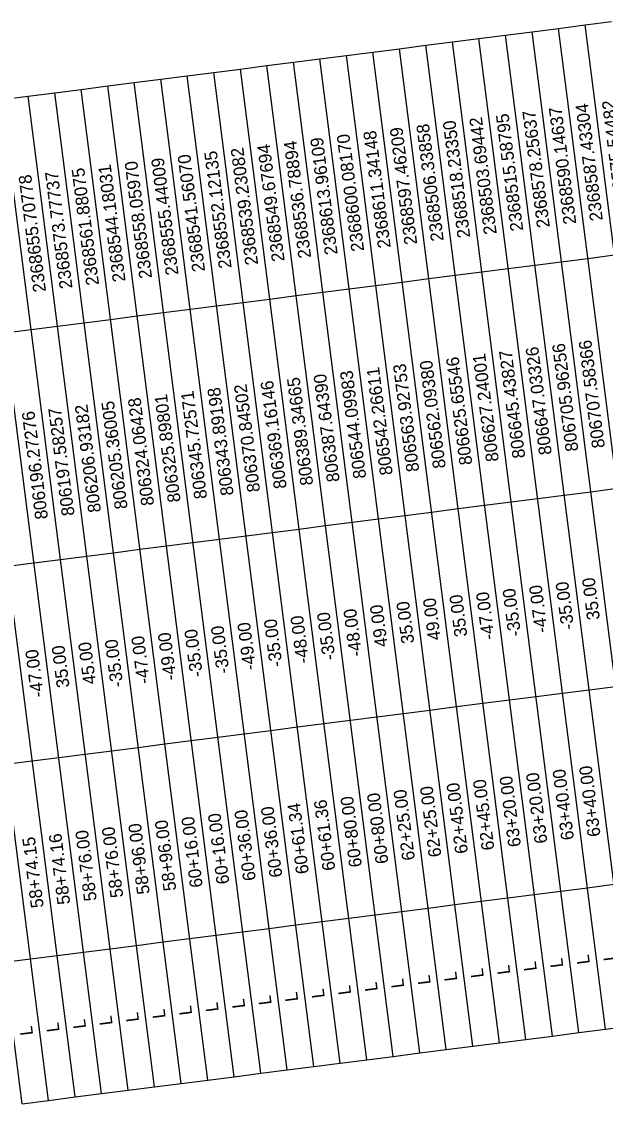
# Model space of a CAD drawing. Extents: x 2364621 to 2374814, y 792603 to 806745.
# Drawn here: x 2368118 to 2369200, y 803235 to 805232 of the extents above; entities that cross this region are included whole.
import ezdxf

# ---------------------------------------------------------------- set-up
doc = ezdxf.new("R2010")
doc.units = 0
doc.layers.add('CTL Sheet Table Cell', color=7, linetype='Continuous')
doc.layers.add('CTL Sheet Text', color=7, linetype='Continuous')

msp = doc.modelspace()

# ---------------------------------------------------------------- linework, layer by layer
at = {"layer": 'CTL Sheet Table Cell'}
for p, q in [((2369063.9, 805212.7), (2369113, 805219)), ((2369113, 805219), (2369162.1, 805225.3)), ((2369347.2, 803385.2), (2369113, 805219)), ((2369162.1, 805225.3), (2369211.2, 805231.5)), ((2369396.3, 803391.5), (2369162.1, 805225.3)), ((2368916.5, 805193.9), (2368965.6, 805200.2)), ((2368965.6, 805200.2), (2369014.8, 805206.4)), ((2369199.8, 803366.4), (2368965.6, 805200.2)), ((2369014.8, 805206.4), (2369063.9, 805212.7)), ((2369249, 803372.7), (2369014.8, 805206.4)), ((2369298.1, 803379), (2369063.9, 805212.7)), ((2368769.2, 805175.1), (2368818.3, 805181.3)), ((2368818.3, 805181.3), (2368867.4, 805187.6)), ((2369052.5, 803347.6), (2368818.3, 805181.3)), ((2368867.4, 805187.6), (2368916.5, 805193.9)), ((2369101.6, 803353.9), (2368867.4, 805187.6)), ((2369150.7, 803360.2), (2368916.5, 805193.9)), ((2368621.8, 805156.2), (2368670.9, 805162.5)), ((2368670.9, 805162.5), (2368720.1, 805168.8)), ((2368905.1, 803328.8), (2368670.9, 805162.5)), ((2368720.1, 805168.8), (2368769.2, 805175.1)), ((2368954.3, 803335.1), (2368720.1, 805168.8)), ((2369003.4, 803341.3), (2368769.2, 805175.1)), ((2368425.3, 805131.2), (2368474.5, 805137.4)), ((2368474.5, 805137.4), (2368523.6, 805143.7)), ((2368708.7, 803303.7), (2368474.5, 805137.4)), ((2368523.6, 805143.7), (2368572.7, 805150)), ((2368757.8, 803310), (2368523.6, 805143.7)), ((2368572.7, 805150), (2368621.8, 805156.2)), ((2368806.9, 803316.2), (2368572.7, 805150)), ((2368856, 803322.5), (2368621.8, 805156.2)), ((2368278, 805112.3), (2368327.1, 805118.6)), ((2368327.1, 805118.6), (2368376.2, 805124.9)), ((2368561.3, 803284.9), (2368327.1, 805118.6)), ((2368376.2, 805124.9), (2368425.3, 805131.2)), ((2368610.4, 803291.1), (2368376.2, 805124.9)), ((2368659.6, 803297.4), (2368425.3, 805131.2)), ((2368130.6, 805093.5), (2368179.8, 805099.8)), ((2368179.8, 805099.8), (2368228.9, 805106.1)), ((2368414, 803266.1), (2368179.8, 805099.8)), ((2368228.9, 805106.1), (2368278, 805112.3)), ((2368463.1, 803272.3), (2368228.9, 805106.1)), ((2368512.2, 803278.6), (2368278, 805112.3)), ((2368266.6, 803247.2), (2368032.4, 805081)), ((2368081.5, 805087.2), (2368130.6, 805093.5)), ((2368315.7, 803253.5), (2368081.5, 805087.2)), ((2368364.8, 803259.8), (2368130.6, 805093.5)), ((2368119.3, 803228.4), (2367885.1, 805062.2)), ((2368168.4, 803234.7), (2367934.2, 805068.4)), ((2368217.5, 803241), (2367983.3, 805074.7)), ((2369167.4, 804793.3), (2369216.5, 804799.6)), ((2369020, 804774.5), (2369069.1, 804780.7)), ((2369069.1, 804780.7), (2369118.2, 804787)), ((2369118.2, 804787), (2369167.4, 804793.3)), ((2368872.7, 804755.7), (2368921.8, 804761.9)), ((2368921.8, 804761.9), (2368970.9, 804768.2)), ((2368970.9, 804768.2), (2369020, 804774.5)), ((2368725.3, 804736.8), (2368774.4, 804743.1)), ((2368774.4, 804743.1), (2368823.5, 804749.4)), ((2368823.5, 804749.4), (2368872.7, 804755.7)), ((2368528.8, 804711.7), (2368578, 804718)), ((2368578, 804718), (2368627.1, 804724.3)), ((2368627.1, 804724.3), (2368676.2, 804730.6)), ((2368676.2, 804730.6), (2368725.3, 804736.8)), ((2368381.5, 804692.9), (2368430.6, 804699.2)), ((2368430.6, 804699.2), (2368479.7, 804705.5)), ((2368479.7, 804705.5), (2368528.8, 804711.7)), ((2368234.1, 804674.1), (2368283.2, 804680.4)), ((2368283.2, 804680.4), (2368332.4, 804686.6)), ((2368332.4, 804686.6), (2368381.5, 804692.9)), ((2368086.8, 804655.3), (2368135.9, 804661.6)), ((2368135.9, 804661.6), (2368185, 804667.8)), ((2368185, 804667.8), (2368234.1, 804674.1)), ((2369123.5, 804355.1), (2369172.6, 804361.3)), ((2369172.6, 804361.3), (2369221.7, 804367.6)), ((2368976.1, 804336.2), (2369025.3, 804342.5)), ((2369025.3, 804342.5), (2369074.4, 804348.8)), ((2369074.4, 804348.8), (2369123.5, 804355.1)), ((2368828.8, 804317.4), (2368877.9, 804323.7)), ((2368877.9, 804323.7), (2368927, 804330)), ((2368927, 804330), (2368976.1, 804336.2)), ((2368632.3, 804292.3), (2368681.4, 804298.6)), ((2368681.4, 804298.6), (2368730.6, 804304.9)), ((2368730.6, 804304.9), (2368779.7, 804311.1)), ((2368779.7, 804311.1), (2368828.8, 804317.4)), ((2368485, 804273.5), (2368534.1, 804279.8)), ((2368534.1, 804279.8), (2368583.2, 804286.1)), ((2368583.2, 804286.1), (2368632.3, 804292.3)), ((2368337.6, 804254.7), (2368386.7, 804261)), ((2368386.7, 804261), (2368435.8, 804267.2)), ((2368435.8, 804267.2), (2368485, 804273.5)), ((2368190.3, 804235.9), (2368239.4, 804242.1)), ((2368239.4, 804242.1), (2368288.5, 804248.4)), ((2368288.5, 804248.4), (2368337.6, 804254.7)), ((2368092, 804223.3), (2368141.1, 804229.6)), ((2368141.1, 804229.6), (2368190.3, 804235.9)), ((2369169.5, 803994.9), (2369218.6, 804001.1)), ((2369022.1, 803976), (2369071.3, 803982.3)), ((2369071.3, 803982.3), (2369120.4, 803988.6)), ((2369120.4, 803988.6), (2369169.5, 803994.9)), ((2368874.8, 803957.2), (2368923.9, 803963.5)), ((2368923.9, 803963.5), (2368973, 803969.8)), ((2368973, 803969.8), (2369022.1, 803976)), ((2368727.4, 803938.4), (2368776.6, 803944.7)), ((2368776.6, 803944.7), (2368825.7, 803950.9)), ((2368825.7, 803950.9), (2368874.8, 803957.2)), ((2368531, 803913.3), (2368580.1, 803919.6)), ((2368580.1, 803919.6), (2368629.2, 803925.9)), ((2368629.2, 803925.9), (2368678.3, 803932.1)), ((2368678.3, 803932.1), (2368727.4, 803938.4)), ((2368383.6, 803894.5), (2368432.7, 803900.8)), ((2368432.7, 803900.8), (2368481.9, 803907)), ((2368481.9, 803907), (2368531, 803913.3)), ((2368236.3, 803875.7), (2368285.4, 803881.9)), ((2368285.4, 803881.9), (2368334.5, 803888.2)), ((2368334.5, 803888.2), (2368383.6, 803894.5)), ((2368088.9, 803856.8), (2368138, 803863.1)), ((2368138, 803863.1), (2368187.1, 803869.4)), ((2368187.1, 803869.4), (2368236.3, 803875.7)), ((2369068.2, 803615.8), (2369117.3, 803622.1)), ((2369117.3, 803622.1), (2369166.4, 803628.4)), ((2369166.4, 803628.4), (2369215.5, 803634.7)), ((2368920.8, 803597), (2368969.9, 803603.3)), ((2368969.9, 803603.3), (2369019, 803609.6)), ((2369019, 803609.6), (2369068.2, 803615.8)), ((2368773.4, 803578.2), (2368822.6, 803584.5)), ((2368822.6, 803584.5), (2368871.7, 803590.7)), ((2368871.7, 803590.7), (2368920.8, 803597)), ((2368626.1, 803559.4), (2368675.2, 803565.7)), ((2368675.2, 803565.7), (2368724.3, 803571.9)), ((2368724.3, 803571.9), (2368773.4, 803578.2)), ((2368429.6, 803534.3), (2368478.7, 803540.6)), ((2368478.7, 803540.6), (2368527.9, 803546.8)), ((2368527.9, 803546.8), (2368577, 803553.1)), ((2368577, 803553.1), (2368626.1, 803559.4)), ((2368282.3, 803515.5), (2368331.4, 803521.7)), ((2368331.4, 803521.7), (2368380.5, 803528)), ((2368380.5, 803528), (2368429.6, 803534.3)), ((2368134.9, 803496.7), (2368184, 803502.9)), ((2368184, 803502.9), (2368233.1, 803509.2)), ((2368233.1, 803509.2), (2368282.3, 803515.5)), ((2368085.8, 803490.4), (2368134.9, 803496.7)), ((2369101.6, 803353.9), (2369150.7, 803360.2)), ((2369150.7, 803360.2), (2369199.8, 803366.4)), ((2369199.8, 803366.4), (2369249, 803372.7)), ((2368954.3, 803335.1), (2369003.4, 803341.3)), ((2369003.4, 803341.3), (2369052.5, 803347.6)), ((2369052.5, 803347.6), (2369101.6, 803353.9)), ((2368806.9, 803316.2), (2368856, 803322.5)), ((2368856, 803322.5), (2368905.1, 803328.8)), ((2368905.1, 803328.8), (2368954.3, 803335.1)), ((2368659.6, 803297.4), (2368708.7, 803303.7)), ((2368708.7, 803303.7), (2368757.8, 803310)), ((2368757.8, 803310), (2368806.9, 803316.2)), ((2368512.2, 803278.6), (2368561.3, 803284.9)), ((2368561.3, 803284.9), (2368610.4, 803291.1)), ((2368610.4, 803291.1), (2368659.6, 803297.4)), ((2368364.8, 803259.8), (2368414, 803266.1)), ((2368414, 803266.1), (2368463.1, 803272.3)), ((2368463.1, 803272.3), (2368512.2, 803278.6)), ((2368168.4, 803234.7), (2368217.5, 803241)), ((2368217.5, 803241), (2368266.6, 803247.2)), ((2368266.6, 803247.2), (2368315.7, 803253.5)), ((2368315.7, 803253.5), (2368364.8, 803259.8)), ((2368119.3, 803228.4), (2368168.4, 803234.7))]:
    msp.add_line(p, q, dxfattribs=at)

# ---------------------------------------------------------------- texts
at = {"layer": 'CTL Sheet Text'}
for s, height, p in [('2368587.43304', 23.579, (2369195.2, 804863.8)), ('2368575.54482', 23.579, (2369244.3, 804870.1)), ('2368515.58795', 23.579, (2369047.9, 804845)), ('2368578.25637', 23.579, (2369097, 804851.3)), ('2368590.14637', 23.579, (2369146.1, 804857.5)), ('2368506.33858', 23.579, (2368900.5, 804826.2)), ('2368518.23350', 23.579, (2368949.6, 804832.4)), ('2368503.69442', 23.579, (2368998.7, 804838.7)), ('2368600.08170', 23.579, (2368753.1, 804807.3)), ('2368611.34148', 23.579, (2368802.3, 804813.6)), ('2368597.46209', 23.579, (2368851.4, 804819.9)), ('2368539.23082', 23.579, (2368556.7, 804782.2)), ('2368549.67694', 23.579, (2368605.8, 804788.5)), ('2368536.78894', 23.579, (2368654.9, 804794.8)), ('2368613.96109', 23.579, (2368704, 804801.1)), ('2368555.44009', 23.579, (2368409.3, 804763.4)), ('2368541.56070', 23.579, (2368458.4, 804769.7)), ('2368552.12135', 23.579, (2368507.6, 804776)), ('2368561.88075', 23.579, (2368262, 804744.6)), ('2368544.18031', 23.579, (2368311.1, 804750.9)), ('2368558.05970', 23.579, (2368360.2, 804757.2)), ('2368655.70778', 23.579, (2368163.7, 804732.1)), ('2368573.77737', 23.579, (2368212.8, 804738.3)), ('806707.58366', 23.579, (2369199, 804443.4)), ('806645.43827', 23.579, (2369051.6, 804424.6)), ('806647.03326', 23.579, (2369100.7, 804430.9)), ('806705.96256', 23.579, (2369149.9, 804437.2)), ('806562.09380', 23.579, (2368904.3, 804405.8)), ('806625.65546', 23.579, (2368953.4, 804412.1)), ('806627.24001', 23.579, (2369002.5, 804418.3)), ('806387.64390', 23.579, (2368707.8, 804380.7)), ('806544.09983', 23.579, (2368756.9, 804387)), ('806542.26611', 23.579, (2368806, 804393.3)), ('806563.92753', 23.579, (2368855.1, 804399.5)), ('806370.84502', 23.579, (2368560.4, 804361.9)), ('806369.16146', 23.579, (2368609.6, 804368.2)), ('806389.34665', 23.579, (2368658.7, 804374.4)), ('806325.89801', 23.579, (2368413.1, 804343.1)), ('806345.72571', 23.579, (2368462.2, 804349.3)), ('806343.89198', 23.579, (2368511.3, 804355.6)), ('806206.93182', 23.579, (2368265.7, 804324.2)), ('806205.36005', 23.579, (2368314.9, 804330.5)), ('806324.06428', 23.579, (2368364, 804336.8)), ('806196.27276', 23.579, (2368167.5, 804311.7)), ('806197.58257', 23.579, (2368216.6, 804318)), ('35.00', 23.58, (2369189.7, 804125.4)), ('-35.00', 23.58, (2369043.8, 804095)), ('-47.00', 23.58, (2369092.9, 804101.3)), ('-35.00', 23.58, (2369142, 804107.6)), ('49.00', 23.58, (2368895, 804087.8)), ('35.00', 23.58, (2368944.1, 804094.1)), ('-47.00', 23.58, (2368994.7, 804088.7)), ('-48.00', 23.58, (2368749.1, 804057.4)), ('49.00', 23.58, (2368796.7, 804075.3)), ('35.00', 23.58, (2368845.8, 804081.5)), ('-49.00', 23.58, (2368552.6, 804032.3)), ('-35.00', 23.58, (2368601.7, 804038.6)), ('-48.00', 23.58, (2368650.9, 804044.8)), ('-35.00', 23.58, (2368700, 804051.1)), ('-49.00', 23.58, (2368405.3, 804013.5)), ('-35.00', 23.58, (2368454.4, 804019.7)), ('-35.00', 23.58, (2368503.5, 804026)), ('45.00', 23.58, (2368256.4, 804006.3)), ('-35.00', 23.58, (2368307, 804000.9)), ('-47.00', 23.58, (2368356.1, 804007.2)), ('-47.00', 23.58, (2368159.7, 803982.1)), ('35.00', 23.58, (2368207.3, 804000)), ('63+20.00', 23.58, (2369092.8, 803711.6)), ('63+40.00', 23.58, (2369141.9, 803717.9)), ('63+40.00', 23.58, (2369191, 803724.2)), ('62+45.00', 23.58, (2368945.4, 803692.8)), ('62+45.00', 23.58, (2368994.5, 803699.1)), ('63+20.00', 23.58, (2369043.6, 803705.3)), ('60+80.00', 23.58, (2368798.1, 803674)), ('62+25.00', 23.58, (2368847.2, 803680.3)), ('62+25.00', 23.58, (2368896.3, 803686.5)), ('60+61.34', 23.58, (2368650.7, 803655.2)), ('60+61.36', 23.58, (2368699.8, 803661.4)), ('60+80.00', 23.58, (2368748.9, 803667.7)), ('60+16.00', 23.58, (2368454.2, 803630.1)), ('60+16.00', 23.58, (2368503.4, 803636.3)), ('60+36.00', 23.58, (2368552.5, 803642.6)), ('60+36.00', 23.58, (2368601.6, 803648.9)), ('58+76.00', 23.58, (2368306.9, 803611.2)), ('58+96.00', 23.58, (2368356, 803617.5)), ('58+96.00', 23.58, (2368405.1, 803623.8)), ('58+74.15', 23.58, (2368159.5, 803592.4)), ('58+74.16', 23.58, (2368208.6, 803598.7)), ('58+76.00', 23.58, (2368257.8, 803605)), ('L', 23.6, (2369171.2, 803488)), ('L', 23.6, (2369220.4, 803494.3)), ('L', 23.6, (2369023.9, 803469.2)), ('L', 23.6, (2369073, 803475.5)), ('L', 23.6, (2369122.1, 803481.8)), ('L', 23.6, (2368827.4, 803444.1)), ('L', 23.6, (2368876.5, 803450.4)), ('L', 23.6, (2368925.7, 803456.7)), ('L', 23.6, (2368974.8, 803462.9)), ('L', 23.6, (2368680.1, 803425.3)), ('L', 23.6, (2368729.2, 803431.6)), ('L', 23.6, (2368778.3, 803437.8)), ('L', 23.6, (2368532.7, 803406.5)), ('L', 23.6, (2368581.8, 803412.8)), ('L', 23.6, (2368630.9, 803419)), ('L', 23.6, (2368385.4, 803387.7)), ('L', 23.6, (2368434.5, 803393.9)), ('L', 23.6, (2368483.6, 803400.2)), ('L', 23.6, (2368238, 803368.8)), ('L', 23.6, (2368287.1, 803375.1)), ('L', 23.6, (2368336.2, 803381.4)), ('L', 23.6, (2368139.8, 803356.3)), ('L', 23.6, (2368188.9, 803362.6))]:
    msp.add_text(s, height=height, rotation=97.2784, dxfattribs=at).set_placement(p)

doc.saveas('drawing.dxf')
